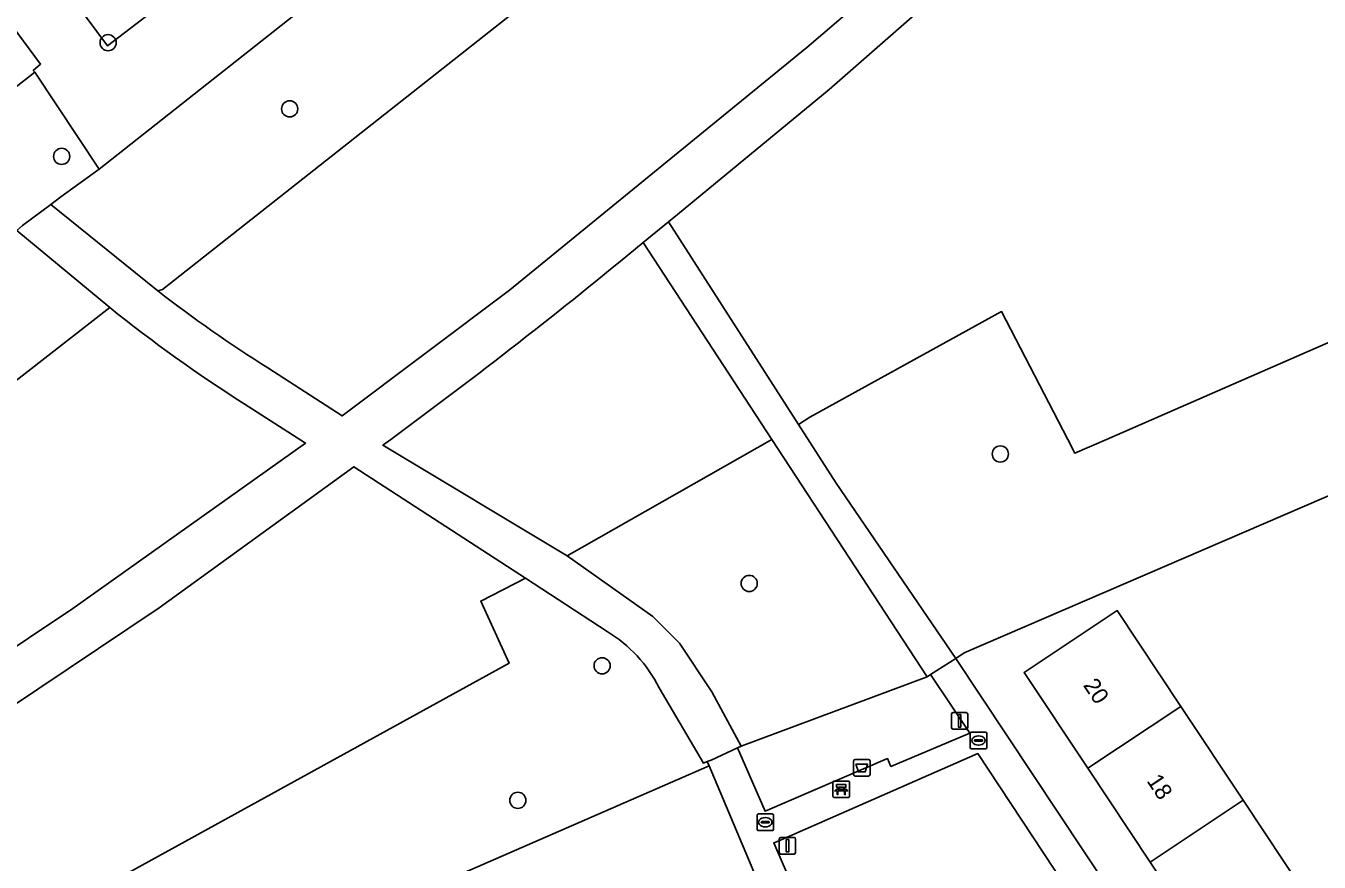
# Model space of a CAD drawing. Extents: x 159352 to 160617, y 385888 to 387323.
# Drawn here: x 159570 to 159648.2, y 386474.4 to 386525 of the extents above; entities that cross this region are included whole.
import ezdxf

# ---------------------------------------------------------------- set-up
doc = ezdxf.new("R2010")
doc.units = 0
for name, color, linetype in [('IMGEO_Afvalbak', 7, 'Continuous'), ('IMGEO_Bank', 7, 'Continuous'), ('IMGEO_Boom', 7, 'Continuous'), ('IMGEO_Erf', 7, 'Continuous'), ('IMGEO_Gemengd_bos', 7, 'Continuous'), ('IMGEO_Groenvoorziening', 7, 'Continuous'), ('IMGEO_Hek', 7, 'Continuous'), ('IMGEO_Kolk', 7, 'Continuous'), ('IMGEO_Lichtmast', 7, 'Continuous'), ('IMGEO_Loofbos', 7, 'Continuous'), ('IMGEO_Pand', 7, 'Continuous'), ('IMGEO_Pand_nummerreeks', 7, 'Continuous'), ('IMGEO_Voetpad_halfverhard', 7, 'Continuous'), ('IMGEO_Voetpad_open', 7, 'Continuous')]:
    doc.layers.add(name, color=color, linetype=linetype)

msp = doc.modelspace()

# ---------------------------------------------------------------- linework, layer by layer
at = {"layer": 'IMGEO_Afvalbak'}
for p, q in [((159620.026, 386479.748), (159620.026, 386480.548)), ((159620.026, 386480.548), (159620.026, 386479.748)), ((159620.126, 386480.648), (159620.916, 386480.648)), ((159620.916, 386480.648), (159620.126, 386480.648)), ((159621.016, 386480.548), (159621.016, 386479.748)), ((159621.016, 386479.748), (159621.016, 386480.548)), ((159620.916, 386479.648), (159620.126, 386479.648)), ((159620.126, 386479.648), (159620.916, 386479.648))]:
    msp.add_line(p, q, dxfattribs=at)
msp.add_lwpolyline([(159620.169, 386480.362), (159620.873, 386480.362), (159620.724, 386479.892), (159620.318, 386479.892), (159620.169, 386480.362)], dxfattribs=at)
for centre, start, end in [((159620.126, 386480.548), 90, 180), ((159620.126, 386480.548), 90, 180), ((159620.916, 386480.548), 0, 90), ((159620.916, 386480.548), 360, 90), ((159620.126, 386479.748), 180, 270), ((159620.126, 386479.748), 180, 270), ((159620.916, 386479.748), 270, 0), ((159620.916, 386479.748), 270, 0)]:
    msp.add_arc(centre, 0.1, start, end, dxfattribs=at)
at = {"layer": 'IMGEO_Bank'}
for p, q in [((159618.777, 386478.421), (159618.777, 386479.262)), ((159618.777, 386479.262), (159618.777, 386478.421)), ((159618.852, 386479.346), (159619.693, 386479.346)), ((159619.693, 386479.346), (159618.852, 386479.346)), ((159619.474, 386478.744), (159619.081, 386478.744)), ((159619.086, 386478.852), (159619.086, 386478.958)), ((159619.13, 386478.958), (159619.13, 386478.852)), ((159619.418, 386478.964), (159619.136, 386478.964)), ((159619.136, 386478.846), (159619.418, 386478.846)), ((159619.424, 386478.852), (159619.424, 386478.958)), ((159619.468, 386478.958), (159619.468, 386478.852)), ((159619.777, 386479.271), (159619.777, 386478.43)), ((159619.777, 386478.43), (159619.777, 386479.271)), ((159619.702, 386478.346), (159618.861, 386478.346)), ((159618.861, 386478.346), (159619.702, 386478.346))]:
    msp.add_line(p, q, dxfattribs=at)
for points in [[(159619.024, 386478.744), (159618.882, 386478.744), (159618.994, 386478.846), (159619.08, 386478.846)], [(159619.08, 386478.964), (159618.994, 386478.964), (159618.994, 386479.125), (159619.557, 386479.125), (159619.557, 386478.964), (159619.474, 386478.964)], [(159619.074, 386478.737), (159619.074, 386478.53), (159619.031, 386478.53), (159619.031, 386478.737)], [(159619.474, 386478.846), (159619.557, 386478.846), (159619.669, 386478.744), (159619.53, 386478.744)], [(159619.524, 386478.737), (159619.524, 386478.53), (159619.48, 386478.53), (159619.48, 386478.737)]]:
    msp.add_lwpolyline(points, dxfattribs=at)
for centre, radius, start, end in [((159618.855, 386479.268), 0.0779, 92.4484, 184.28452), ((159618.855, 386479.268), 0.0779, 92.4484, 184.28452), ((159619.024, 386478.737), 0.00671, 2.89567, 87.10433), ((159619.081, 386478.737), 0.00671, 92.89567, 177.10433), ((159619.079, 386478.957), 0.00671, 2.89567, 87.10433), ((159619.079, 386478.853), 0.00671, 272.89567, 357.10433), ((159619.136, 386478.957), 0.00671, 92.89567, 177.10433), ((159619.136, 386478.853), 0.00671, 182.89567, 267.10433), ((159619.418, 386478.957), 0.00671, 2.89567, 87.10433), ((159619.418, 386478.853), 0.00671, 272.89567, 357.10433), ((159619.475, 386478.957), 0.00671, 92.89567, 177.10433), ((159619.475, 386478.853), 0.00671, 182.89567, 267.10433), ((159619.473, 386478.737), 0.00671, 2.89567, 87.10433), ((159619.53, 386478.737), 0.00671, 92.89567, 177.10433), ((159619.699, 386479.268), 0.0779, 2.4484, 94.28452), ((159619.699, 386479.268), 0.0779, 2.4484, 94.28452), ((159618.855, 386478.424), 0.0779, 182.4484, 274.28452), ((159618.855, 386478.424), 0.0779, 182.4484, 274.28452), ((159619.699, 386478.424), 0.0779, 272.4484, 4.28452), ((159619.699, 386478.424), 0.0779, 272.4484, 4.28452)]:
    msp.add_arc(centre, radius, start, end, dxfattribs=at)
at = {"layer": 'IMGEO_Boom'}
for centre in [(159574.963, 386523.99), (159585.939, 386519.991), (159572.157, 386517.116), (159628.891, 386499.122), (159613.716, 386491.293), (159604.823, 386486.312), (159599.729, 386478.177)]:
    msp.add_circle(centre, 0.489, dxfattribs=at)
at = {"layer": 'IMGEO_Erf'}
for points in [[(159653.254, 386498.542), (159626.707, 386487.098), (159626.206, 386486.751), (159655.569, 386442.516)], [(159616.53, 386467.818), (159611.284, 386480.27), (159588.978, 386470.532)]]:
    msp.add_lwpolyline(points, dxfattribs=at)
msp.add_lwpolyline([(159654.877, 386461.172), (159658.644, 386455.5), (159662.493, 386449.706), (159656.862, 386445.965), (159653.012, 386451.762), (159649.244, 386457.433), (159645.478, 386463.104), (159641.711, 386468.774), (159637.944, 386474.446), (159634.177, 386480.117), (159630.329, 386485.91), (159635.96, 386489.651), (159639.81, 386483.855), (159643.577, 386478.184), (159647.344, 386472.513), (159651.111, 386466.842)], close=True, dxfattribs=at)
at = {"layer": 'IMGEO_Gemengd_bos'}
msp.add_lwpolyline([(159516.017, 386479.434), (159570.525, 386522.203), (159570.435, 386522.318), (159570.881, 386522.697), (159555.785, 386543.119)], dxfattribs=at)
for points in [[(159553.746, 386500), (159569.438, 386512.645), (159569.791, 386512.93), (159571.496, 386514.211), (159572.106, 386514.67), (159574.43, 386516.35), (159570.525, 386522.203), (159516.017, 386479.434), (159511.521, 386482.123), (159510.374, 386475.983), (159510.308, 386475.628), (159510.81, 386475.39), (159511.126, 386475.635), (159514.222, 386478.04), (159521.717, 386474.152)], [(159575.069, 386507.971), (159569.438, 386512.645), (159553.746, 386500), (159521.717, 386474.152), (159527.677, 386471.06), (159564.819, 386500)]]:
    msp.add_lwpolyline(points, close=True, dxfattribs=at)
at = {"layer": 'IMGEO_Groenvoorziening'}
for points in [[(159656.794, 386519.346), (159667.147, 386524.973), (159649.609, 386549.736), (159637.343, 386537.912), (159628.208, 386529.625), (159618.553, 386521.16), (159609.376, 386513.596), (159608.831, 386513.153), (159616.698, 386500.899), (159617.387, 386501.341), (159628.972, 386507.732), (159632.966, 386500), (159633.396, 386499.166), (159635.305, 386500), (159660.037, 386510.81)], [(159674.684, 386507.863), (159678.18, 386509.396), (159667.147, 386524.973), (159656.794, 386519.346), (159660.037, 386510.81), (159635.305, 386500), (159633.396, 386499.166), (159632.966, 386500), (159628.972, 386507.732), (159617.387, 386501.341), (159616.698, 386500.899), (159618.977, 386497.348), (159626.206, 386486.751), (159626.707, 386487.098), (159653.254, 386498.542), (159653.195, 386498.679), (159655.69, 386499.757), (159655.753, 386499.612)], [(159615.073, 386500), (159602.715, 386492.962), (159607.893, 386489.301), (159609.499, 386487.683), (159611.459, 386484.74), (159613.22, 386481.445), (159624.463, 386485.638)], [(159563.351, 386479.984), (159568.818, 386469.742), (159599.199, 386486.465), (159597.482, 386490.226), (159600.187, 386491.603), (159589.808, 386498.351), (159578.056, 386489.827)], [(159627.041, 386482.24), (159624.664, 386485.777), (159624.463, 386485.638), (159613.22, 386481.445), (159613.016, 386481.357), (159614.676, 386477.518), (159622.066, 386480.699), (159622.275, 386480.229)], [(159627.534, 386481.006), (159615.457, 386475.714), (159615.201, 386475.602), (159619.656, 386465.294), (159624.96, 386452.966), (159625.229, 386453.082), (159641.381, 386460.032)]]:
    msp.add_lwpolyline(points, close=True, dxfattribs=at)
for points in [[(159584.623, 386504.325), (159589.105, 386501.423), (159599.231, 386509.03), (159617.205, 386523.694), (159621.215, 386527.155), (159634.736, 386539.418), (159625.523, 386546.373), (159578.254, 386509.068), (159577.978, 386508.983)], [(159569.304, 386531.385), (159574.935, 386523.799), (159588.034, 386533.868)], [(159592.047, 386500), (159591.571, 386499.651), (159602.715, 386492.962), (159615.073, 386500), (159607.306, 386511.913)], [(159575.069, 386507.971), (159564.819, 386500), (159527.677, 386471.06), (159534.706, 386467.413), (159542.745, 386471.47)], [(159554.059, 386477.493), (159562.202, 386482.68), (159572.831, 386489.777), (159586.902, 386499.781), (159583.177, 386502.15)], [(159605.128, 386488.391), (159600.187, 386491.603), (159597.482, 386490.226), (159599.199, 386486.465), (159568.818, 386469.742), (159563.351, 386479.984), (159561.157, 386478.515)], [(159611.284, 386480.27), (159611.179, 386480.521), (159610.943, 386480.427), (159608.263, 386484.977)], [(159550.307, 386472.086), (159559.004, 386458.779), (159558.754, 386458.6), (159559.134, 386458.028), (159568.384, 386461.893), (159567.761, 386462.828), (159569.941, 386464.28), (159586.179, 386469.337), (159588.978, 386470.532), (159611.284, 386480.27)]]:
    msp.add_lwpolyline(points, dxfattribs=at)
for centre, radius, start, end in [((159396.328, 386766.419), 330.583, 306.30202, 309.65769), ((159626.206, 386570.716), 78.338, 232.00145, 237.93932), ((159633.766, 386581.172), 93.828, 231.27527, 237.37311), ((159600.813, 386481.282), 8.316, 26.37924, 58.74189)]:
    msp.add_arc(centre, radius, start, end, dxfattribs=at)
at = {"layer": 'IMGEO_Hek'}
for points in [[(159574.43, 386516.35), (159662.25, 386585.73)], [(159484.614, 386498.362), (159500, 386489.012), (159516.017, 386479.434), (159570.525, 386522.203)], [(159570.525, 386522.203), (159574.43, 386516.35)]]:
    msp.add_lwpolyline(points, dxfattribs=at)
at = {"layer": 'IMGEO_Kolk'}
for p, q in [((159627.077, 386481.368), (159627.077, 386482.22)), ((159627.152, 386482.294), (159628.004, 386482.294)), ((159627.379, 386481.837), (159627.777, 386481.837)), ((159627.565, 386482.074), (159627.59, 386482.074)), ((159628.078, 386482.22), (159628.078, 386481.368)), ((159628.004, 386481.294), (159627.152, 386481.294)), ((159627.336, 386481.788), (159627.336, 386481.8)), ((159627.774, 386481.751), (159627.376, 386481.751)), ((159627.588, 386481.514), (159627.563, 386481.514)), ((159627.82, 386481.8), (159627.82, 386481.788)), ((159614.185, 386476.425), (159614.185, 386477.277)), ((159614.26, 386477.351), (159615.112, 386477.351)), ((159615.186, 386477.277), (159615.186, 386476.425)), ((159614.444, 386476.845), (159614.444, 386476.857)), ((159614.882, 386476.808), (159614.484, 386476.808)), ((159614.487, 386476.894), (159614.885, 386476.894)), ((159614.696, 386476.571), (159614.671, 386476.571)), ((159614.673, 386477.131), (159614.698, 386477.131)), ((159614.928, 386476.857), (159614.928, 386476.845)), ((159615.112, 386476.351), (159614.26, 386476.351))]:
    msp.add_line(p, q, dxfattribs=at)
for points in [[(159627.077, 386481.368), (159627.077, 386482.22)], [(159627.152, 386482.294), (159628.004, 386482.294)], [(159628.078, 386482.22), (159628.078, 386481.368)], [(159628.004, 386481.294), (159627.152, 386481.294)], [(159614.185, 386476.425), (159614.185, 386477.277)], [(159614.26, 386477.351), (159615.112, 386477.351)], [(159615.186, 386477.277), (159615.186, 386476.425)], [(159615.112, 386476.351), (159614.26, 386476.351)]]:
    msp.add_lwpolyline(points, dxfattribs=at)
for centre, radius, start, end in [((159627.154, 386482.218), 0.0765, 91.55205, 178.44795), ((159627.154, 386482.218), 0.0765, 91.55205, 178.44795), ((159627.376, 386481.797), 0.0403, 85.87752, 175.75265), ((159627.781, 386481.799), 0.0386, 1.73085, 96.63898), ((159628.002, 386482.218), 0.0765, 1.55205, 88.44795), ((159628.002, 386482.218), 0.0765, 1.55205, 88.44795), ((159627.154, 386481.37), 0.0765, 181.55205, 268.44795), ((159627.154, 386481.37), 0.0765, 181.55205, 268.44795), ((159627.373, 386481.787), 0.0366, 178.93798, 274.71019), ((159627.777, 386481.794), 0.043, 264.86636, 352.45326), ((159628.002, 386481.37), 0.0765, 271.55205, 358.44795), ((159628.002, 386481.37), 0.0765, 271.55205, 358.44795), ((159614.262, 386477.275), 0.0765, 91.55205, 178.44795), ((159614.262, 386477.275), 0.0765, 91.55205, 178.44795), ((159615.11, 386477.275), 0.0765, 1.55205, 88.44795), ((159615.11, 386477.275), 0.0765, 1.55205, 88.44795), ((159614.262, 386476.427), 0.0765, 181.55205, 268.44795), ((159614.262, 386476.427), 0.0765, 181.55205, 268.44795), ((159614.484, 386476.854), 0.0403, 85.87752, 175.75265), ((159614.481, 386476.844), 0.0366, 178.93798, 274.71019), ((159614.885, 386476.851), 0.043, 264.86636, 352.45326), ((159614.889, 386476.856), 0.0386, 1.73085, 96.63898), ((159615.11, 386476.427), 0.0765, 271.55205, 358.44795), ((159615.11, 386476.427), 0.0765, 271.55205, 358.44795)]:
    msp.add_arc(centre, radius, start, end, dxfattribs=at)
for centre, major_axis, ratio, start_param, end_param in [((159627.564, 386481.794), (-0.387, 0.002), 0.722429, 4.712389, 7.853982), ((159627.589, 386481.794), (-0.39, 0.002), 0.717154, 1.570796, 4.712389), ((159614.672, 386476.851), (-0.387, 0.002), 0.722429, 4.712389, 7.853982), ((159614.697, 386476.851), (-0.39, 0.002), 0.717154, 1.570796, 4.712389)]:
    msp.add_ellipse(centre, major_axis=major_axis, ratio=ratio, start_param=start_param, end_param=end_param, dxfattribs=at)
at = {"layer": 'IMGEO_Lichtmast'}
for p, q in [((159626.035, 386483.484), (159626.825, 386483.484)), ((159626.825, 386483.484), (159626.035, 386483.484)), ((159625.935, 386482.584), (159625.935, 386483.384)), ((159625.935, 386483.384), (159625.935, 386482.584)), ((159626.925, 386483.384), (159626.925, 386482.584)), ((159626.925, 386482.584), (159626.925, 386483.384)), ((159626.825, 386482.484), (159626.035, 386482.484)), ((159626.035, 386482.484), (159626.825, 386482.484)), ((159615.532, 386475.029), (159615.532, 386475.829)), ((159615.532, 386475.829), (159615.532, 386475.029)), ((159615.632, 386475.929), (159616.422, 386475.929)), ((159616.422, 386475.929), (159615.632, 386475.929)), ((159616.522, 386475.829), (159616.522, 386475.029)), ((159616.522, 386475.029), (159616.522, 386475.829)), ((159616.422, 386474.929), (159615.632, 386474.929)), ((159615.632, 386474.929), (159616.422, 386474.929))]:
    msp.add_line(p, q, dxfattribs=at)
for points in [[(159626.355, 386483.359), (159626.505, 386483.359), (159626.505, 386482.609), (159626.355, 386482.609), (159626.355, 386483.359)], [(159615.952, 386475.804), (159616.102, 386475.804), (159616.102, 386475.054), (159615.952, 386475.054), (159615.952, 386475.804)]]:
    msp.add_lwpolyline(points, dxfattribs=at)
for centre, start, end in [((159626.035, 386483.384), 90, 180), ((159626.035, 386483.384), 90, 180), ((159626.825, 386483.384), 0, 90), ((159626.825, 386483.384), 360, 90), ((159626.035, 386482.584), 180, 270), ((159626.035, 386482.584), 180, 270), ((159626.825, 386482.584), 270, 0), ((159626.825, 386482.584), 270, 0), ((159615.632, 386475.829), 90, 180), ((159615.632, 386475.829), 90, 180), ((159616.422, 386475.829), 0, 90), ((159616.422, 386475.829), 360, 90), ((159615.632, 386475.029), 180, 270), ((159615.632, 386475.029), 180, 270), ((159616.422, 386475.029), 270, 0), ((159616.422, 386475.029), 270, 0)]:
    msp.add_arc(centre, 0.1, start, end, dxfattribs=at)
at = {"layer": 'IMGEO_Loofbos'}
msp.add_lwpolyline([(159664.489, 386567.947), (159681.27, 386584.321), (159690.686, 386592.788), (159706.682, 386605.448), (159699.344, 386615.986), (159682.84, 386603.474), (159683.37, 386602.415), (159662.25, 386585.73), (159574.43, 386516.35), (159572.106, 386514.67), (159571.496, 386514.211), (159576.62, 386510.069), (159577.978, 386508.983), (159578.254, 386509.068), (159625.523, 386546.373), (159634.736, 386539.418)], close=True, dxfattribs=at)
at = {"layer": 'IMGEO_Pand'}
for points in [[(159639.81, 386483.855), (159635.96, 386489.651), (159630.329, 386485.91), (159634.177, 386480.117)], [(159643.577, 386478.184), (159639.81, 386483.855), (159634.177, 386480.117), (159637.944, 386474.446)], [(159637.944, 386474.446), (159641.711, 386468.774), (159647.344, 386472.513), (159643.577, 386478.184)]]:
    msp.add_lwpolyline(points, close=True, dxfattribs=at)
at = {"layer": 'IMGEO_Voetpad_halfverhard'}
for points in [[(159607.306, 386511.913), (159608.831, 386513.153), (159609.376, 386513.596), (159618.553, 386521.16), (159628.208, 386529.625), (159637.343, 386537.912), (159649.609, 386549.736), (159651.927, 386551.906), (159679.699, 386578.71), (159691.633, 386589.707), (159700.378, 386596.969), (159706.083, 386601.493), (159714.799, 386608.404), (159719.418, 386611.743), (159723.124, 386614.022), (159721.923, 386616.373)], [(159711.795, 386609.495), (159706.682, 386605.448), (159690.686, 386592.788), (159681.27, 386584.321), (159664.489, 386567.947), (159634.736, 386539.418), (159621.215, 386527.155), (159617.205, 386523.694), (159599.231, 386509.03), (159589.105, 386501.423), (159584.623, 386504.325)], [(159555.785, 386543.119), (159570.881, 386522.697), (159570.435, 386522.318), (159570.525, 386522.203), (159574.43, 386516.35), (159662.25, 386585.73)], [(159588.034, 386533.868), (159574.935, 386523.799), (159569.304, 386531.385)], [(159577.978, 386508.983), (159576.62, 386510.069), (159571.496, 386514.211), (159569.791, 386512.93), (159569.438, 386512.645), (159575.069, 386507.971)], [(159583.177, 386502.15), (159586.902, 386499.781), (159572.831, 386489.777), (159562.202, 386482.68), (159554.059, 386477.493)], [(159608.263, 386484.977), (159610.943, 386480.427), (159611.179, 386480.521), (159611.414, 386480.615), (159613.016, 386481.357), (159613.22, 386481.445), (159611.459, 386484.74), (159609.499, 386487.683), (159607.893, 386489.301), (159602.715, 386492.962), (159591.571, 386499.651), (159592.047, 386500)], [(159561.157, 386478.515), (159563.351, 386479.984), (159578.056, 386489.827), (159589.808, 386498.351), (159600.187, 386491.603), (159605.128, 386488.391)]]:
    msp.add_lwpolyline(points, dxfattribs=at)
msp.add_lwpolyline([(159616.698, 386500.899), (159608.831, 386513.153), (159607.306, 386511.913), (159615.073, 386500), (159624.463, 386485.638), (159624.664, 386485.777), (159626.206, 386486.751), (159618.977, 386497.348)], close=True, dxfattribs=at)
for centre, radius, start, end in [((159396.328, 386766.419), 330.583, 306.30202, 309.65769), ((159626.206, 386570.716), 78.338, 232.00145, 237.93932), ((159633.766, 386581.172), 93.828, 231.27527, 237.37311), ((159600.813, 386481.282), 8.316, 26.37924, 58.74189)]:
    msp.add_arc(centre, radius, start, end, dxfattribs=at)
at = {"layer": 'IMGEO_Voetpad_open'}
msp.add_lwpolyline([(159655.569, 386442.516), (159626.206, 386486.751), (159624.664, 386485.777), (159627.041, 386482.24), (159622.275, 386480.229), (159622.066, 386480.699), (159614.676, 386477.518), (159613.016, 386481.357), (159611.414, 386480.615), (159611.179, 386480.521), (159611.284, 386480.27), (159616.53, 386467.818), (159623.619, 386452.36), (159624.218, 386450.973), (159626.632, 386444.407), (159631.354, 386433.532)], dxfattribs=at)
msp.add_lwpolyline([(159625.229, 386453.082), (159624.96, 386452.966), (159619.656, 386465.294), (159615.201, 386475.602), (159615.457, 386475.714), (159627.534, 386481.006), (159641.381, 386460.032)], close=True, dxfattribs=at)

# ---------------------------------------------------------------- texts
at = {"layer": 'IMGEO_Pand_nummerreeks'}
for s, p in [('20', (159633.868, 386485.137)), ('18', (159637.708, 386479.355))]:
    msp.add_text(s, height=1, rotation=303.59364, dxfattribs=at).set_placement(p)

doc.saveas('drawing.dxf')
